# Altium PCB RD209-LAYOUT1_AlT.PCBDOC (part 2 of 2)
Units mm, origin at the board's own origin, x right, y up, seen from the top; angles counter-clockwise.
Board outline 152.4 x 152.4 mm, 4 copper layers (TOP, Mid-Layer 1, Mid-Layer 2, BOTTOM), stack 0.711 mm thick; 246 components, 168 nets, 761 pads, 266 vias.
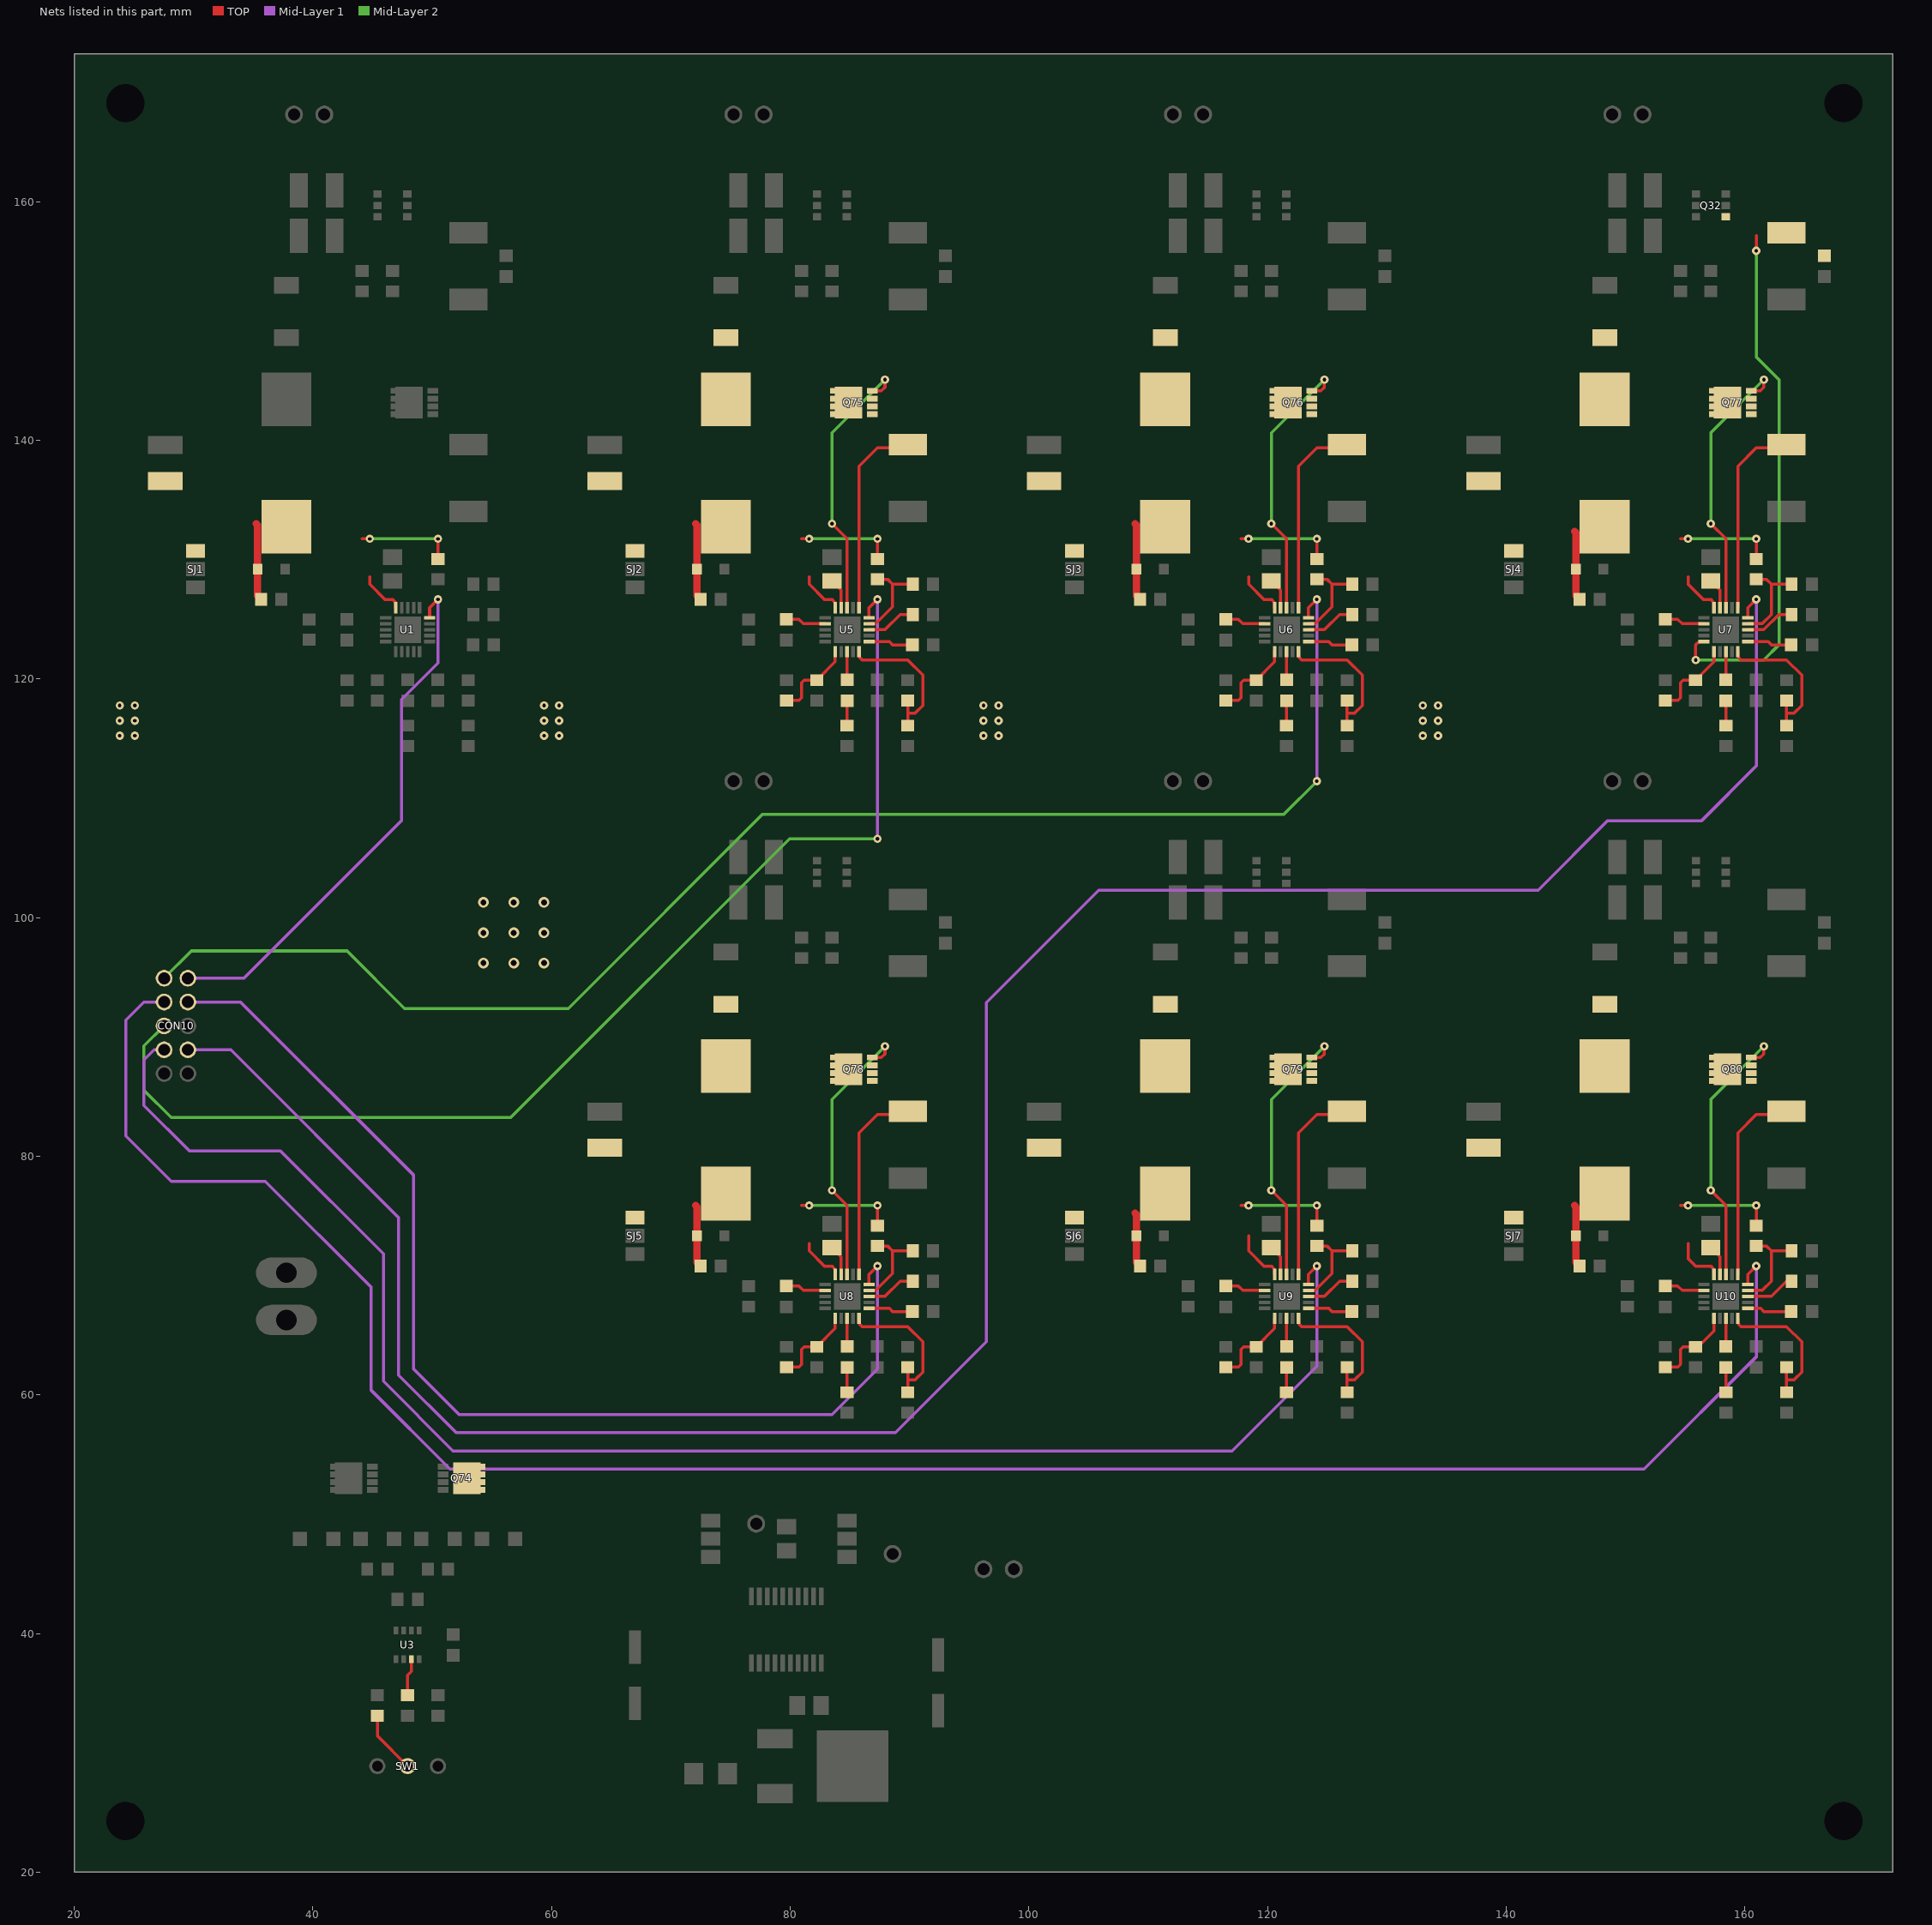
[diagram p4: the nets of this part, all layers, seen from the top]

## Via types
v1: diameter 0.7, hole 0.3, TOP to BOTTOM, tented both sides, 257 vias
v2: diameter 0.9, hole 0.5, TOP to BOTTOM, 9 vias

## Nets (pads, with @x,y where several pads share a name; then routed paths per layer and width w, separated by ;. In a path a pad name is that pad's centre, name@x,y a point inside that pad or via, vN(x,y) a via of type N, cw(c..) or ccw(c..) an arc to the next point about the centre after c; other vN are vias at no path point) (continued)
N_249: R131.1 R132.1 U5.5 | length 12.6
  TOP w0.254: U5.5@85.77,122.3 85.77,121.87 86.04,121.6 89.85,121.6 91.12,120.33 91.12,117.79 90.485,117.155 89.85,117.155 ; R132.1@89.85,116.1 89.85,117.155 ; R131.1@89.85,118.21 89.85,117.155
N_251: C27.2 U5.14 | length 2.6
  TOP w0.254: C27.2@83.5,128.22 84.27,127.45 U5.14@84.27,125.98
N_252: R133.1 U5.8 | length 4.2
  TOP w0.254: U5.8@86.61,124.14 87.945,124.14 89.215,125.41 R133.1@90.27,125.41
N_253: C28.2 U5.6 | length 3.7
  TOP w0.254: U5.6@86.61,123.14 88.31,123.14 88.58,122.87 C28.2@90.245,122.87
N_254: R134.2 R135.1 U5.9 | length 7.6
  TOP w0.254: U5.9@86.61,124.64 87.175,124.64 88.58,126.045 88.58,127.95 ; R135.1@87.31,128.37 88.16,128.37 88.58,127.95 ; R134.2@90.27,127.95 88.58,127.95
N_255: Q75.4 U5.13 | length 23.3
  TOP w0.254: v1(83.5,133.03) 84.77,131.76 U5.13@84.77,125.98 ; Q75.4@86.89,144.165 87.65,144.165 87.945,144.46 v1(87.945,145.095)
  Mid-Layer 2 w0.254: v1(83.5,133.03) 83.5,140.65 v1(87.945,145.095)
N_256: D48.A L2.2 Q75.5 Q75.6 Q75.7 Q75.8 Q75.EP
N_257: Q75.1 Q75.2 Q75.3 R137.2 U5.11 | length 16.7
  TOP w0.254: U5.11@85.77,125.98 85.77,137.84 87.31,139.38 89.59,139.38 R137.2@89.85,139.64
N_258: C30.2 U5.3 | length 2.4
  TOP w0.254: C30.2@84.77,119.935 U5.3@84.77,122.3
N_259: C30.1 R136.2 | length 2.1
  TOP w0.254: R136.2@84.77,116.1 C30.1@84.77,118.185
N_260: C31.2 U5.17 | length 3.4
  TOP w0.254: C31.2@79.69,125.015 80.72,125.015 81.095,124.64 U5.17@82.93,124.64
N_261: R138.2 R139.1 U5.1 | length 7
  TOP w0.254: R139.1@79.69,118.21 80.745,118.21 80.96,118.425 80.96,119.695 81.175,119.91 R138.2@82.23,119.91 83.77,121.45 U5.1@83.77,122.3
N_264: R140.1 R141.1 U6.5 | length 12.6
  TOP w0.254: U6.5@122.6,122.3 122.6,121.87 122.87,121.6 126.68,121.6 127.95,120.33 127.95,117.79 127.315,117.155 126.68,117.155 ; R141.1@126.68,116.1 126.68,117.155 ; R140.1@126.68,118.21 126.68,117.155
N_266: C34.2 U6.14 | length 2.6
  TOP w0.254: C34.2@120.33,128.22 121.1,127.45 U6.14@121.1,125.98
N_267: R142.1 U6.8 | length 4.2
  TOP w0.254: U6.8@123.44,124.14 124.775,124.14 126.045,125.41 R142.1@127.1,125.41
N_268: C35.2 U6.6 | length 3.7
  TOP w0.254: U6.6@123.44,123.14 125.14,123.14 125.41,122.87 C35.2@127.075,122.87
N_269: R143.2 R144.1 U6.9 | length 7.6
  TOP w0.254: U6.9@123.44,124.64 124.005,124.64 125.41,126.045 125.41,127.95 ; R144.1@124.14,128.37 124.99,128.37 125.41,127.95 ; R143.2@127.1,127.95 125.41,127.95
N_270: Q76.4 U6.13 | length 23.3
  TOP w0.254: v1(120.33,133.03) 121.6,131.76 U6.13@121.6,125.98 ; Q76.4@123.72,144.165 124.48,144.165 124.775,144.46 v1(124.775,145.095)
  Mid-Layer 2 w0.254: v1(120.33,133.03) 120.33,140.65 v1(124.775,145.095)
N_271: D49.A L3.2 Q76.5 Q76.6 Q76.7 Q76.8 Q76.EP
N_272: Q76.1 Q76.2 Q76.3 R146.2 U6.11 | length 16.7
  TOP w0.254: U6.11@122.6,125.98 122.6,137.84 124.14,139.38 126.42,139.38 R146.2@126.68,139.64
N_273: C37.2 U6.3 | length 2.4
  TOP w0.254: C37.2@121.6,119.935 U6.3@121.6,122.3
N_274: C37.1 R145.2 | length 2.1
  TOP w0.254: R145.2@121.6,116.1 C37.1@121.6,118.185
N_275: C38.2 U6.17 | length 3.4
  TOP w0.254: C38.2@116.52,125.015 117.55,125.015 117.925,124.64 U6.17@119.76,124.64
N_276: R147.2 R148.1 U6.1 | length 7
  TOP w0.254: R148.1@116.52,118.21 117.575,118.21 117.79,118.425 117.79,119.695 118.005,119.91 R147.2@119.06,119.91 120.6,121.45 U6.1@120.6,122.3
N_279: R149.1 R150.1 U7.5 | length 12.6
  TOP w0.254: U7.5@159.43,122.3 159.43,121.87 159.7,121.6 163.51,121.6 164.78,120.33 164.78,117.79 164.145,117.155 163.51,117.155 ; R150.1@163.51,116.1 163.51,117.155 ; R149.1@163.51,118.21 163.51,117.155
N_281: C41.2 U7.14 | length 2.6
  TOP w0.254: C41.2@157.16,128.22 157.93,127.45 U7.14@157.93,125.98
N_282: R151.1 U7.8 | length 4.2
  TOP w0.254: U7.8@160.27,124.14 161.605,124.14 162.875,125.41 R151.1@163.93,125.41
N_283: C42.2 U7.6 | length 3.7
  TOP w0.254: U7.6@160.27,123.14 161.97,123.14 162.24,122.87 C42.2@163.905,122.87
N_284: R152.2 R153.1 U7.9 | length 8
  TOP w0.254: U7.9@160.27,124.64 161.47,124.64 162.24,125.41 162.24,127.95 ; R153.1@160.97,128.37 161.82,128.37 162.24,127.95 ; R152.2@163.93,127.95 162.24,127.95
N_285: Q77.4 U7.13 | length 23.3
  TOP w0.254: v1(157.16,133.03) 158.43,131.76 U7.13@158.43,125.98 ; Q77.4@160.55,144.165 161.31,144.165 161.605,144.46 v1(161.605,145.095)
  Mid-Layer 2 w0.254: v1(157.16,133.03) 157.16,140.65 v1(161.605,145.095)
N_286: D50.A L4.2 Q77.5 Q77.6 Q77.7 Q77.8 Q77.EP
N_287: Q77.1 Q77.2 Q77.3 R155.2 U7.11 | length 16.7
  TOP w0.254: U7.11@159.43,125.98 159.43,137.84 160.97,139.38 163.25,139.38 R155.2@163.51,139.64
N_288: C44.2 U7.3 | length 2.4
  TOP w0.254: C44.2@158.43,119.935 U7.3@158.43,122.3
N_289: C44.1 R154.2 | length 2.1
  TOP w0.254: R154.2@158.43,116.1 C44.1@158.43,118.185
N_290: C45.2 U7.17 | length 3.4
  TOP w0.254: C45.2@153.35,125.015 154.38,125.015 154.755,124.64 U7.17@156.59,124.64
N_291: R156.2 R157.1 U7.1 | length 7
  TOP w0.254: R157.1@153.35,118.21 154.405,118.21 154.62,118.425 154.62,119.695 154.835,119.91 R156.2@155.89,119.91 157.43,121.45 U7.1@157.43,122.3
N_292: C11.2 Q32.4 R67.2 U7.20 | length 44.7
  TOP w0.254: v1(155.89,121.6) 155.89,122.87 156.16,123.14 U7.20@156.59,123.14 ; v1(160.97,155.89) 160.97,157.16
  Mid-Layer 2 w0.254: v1(155.89,121.6) 161.605,121.6 162.875,122.87 162.875,145.095 160.97,147 v1(160.97,155.89)
N_294: R158.1 R159.1 U8.5 | length 12.6
  TOP w0.254: U8.5@85.77,66.42 85.77,65.99 86.04,65.72 89.85,65.72 91.12,64.45 91.12,61.91 90.485,61.275 89.85,61.275 ; R159.1@89.85,60.22 89.85,61.275 ; R158.1@89.85,62.33 89.85,61.275
N_296: C48.2 U8.14 | length 2.6
  TOP w0.254: C48.2@83.5,72.34 84.27,71.57 U8.14@84.27,70.1
N_297: R160.1 U8.8 | length 4.2
  TOP w0.254: U8.8@86.61,68.26 87.945,68.26 89.215,69.53 R160.1@90.27,69.53
N_298: C49.2 U8.6 | length 3.7
  TOP w0.254: U8.6@86.61,67.26 88.31,67.26 88.58,66.99 C49.2@90.245,66.99
N_299: R161.2 R162.1 U8.9 | length 7.6
  TOP w0.254: U8.9@86.61,68.76 87.175,68.76 88.58,70.165 88.58,72.07 ; R162.1@87.31,72.49 88.16,72.49 88.58,72.07 ; R161.2@90.27,72.07 88.58,72.07
N_300: Q78.4 U8.13 | length 23.3
  TOP w0.254: v1(83.5,77.15) 84.77,75.88 U8.13@84.77,70.1 ; Q78.4@86.89,88.285 87.65,88.285 87.945,88.58 v1(87.945,89.215)
  Mid-Layer 2 w0.254: v1(83.5,77.15) 83.5,84.77 v1(87.945,89.215)
N_301: D51.A L5.2 Q78.5 Q78.6 Q78.7 Q78.8 Q78.EP
N_302: Q78.1 Q78.2 Q78.3 R164.2 U8.11 | length 16.7
  TOP w0.254: U8.11@85.77,70.1 85.77,81.96 87.31,83.5 89.59,83.5 R164.2@89.85,83.76
N_303: C51.2 U8.3 | length 2.4
  TOP w0.254: C51.2@84.77,64.055 U8.3@84.77,66.42
N_304: C51.1 R163.2 | length 2.1
  TOP w0.254: R163.2@84.77,60.22 C51.1@84.77,62.305
N_305: C52.2 U8.17 | length 3.4
  TOP w0.254: C52.2@79.69,69.135 80.72,69.135 81.095,68.76 U8.17@82.93,68.76
N_306: R165.2 R166.1 U8.1 | length 7
  TOP w0.254: R166.1@79.69,62.33 80.745,62.33 80.96,62.545 80.96,63.815 81.175,64.03 R165.2@82.23,64.03 83.77,65.57 U8.1@83.77,66.42
N_309: R167.1 R168.1 U9.5 | length 12.6
  TOP w0.254: U9.5@122.6,66.42 122.6,65.99 122.87,65.72 126.68,65.72 127.95,64.45 127.95,61.91 127.315,61.275 126.68,61.275 ; R168.1@126.68,60.22 126.68,61.275 ; R167.1@126.68,62.33 126.68,61.275
N_311: C55.2 U9.14 | length 2.6
  TOP w0.254: C55.2@120.33,72.34 121.1,71.57 U9.14@121.1,70.1
N_312: R169.1 U9.8 | length 4.2
  TOP w0.254: U9.8@123.44,68.26 124.775,68.26 126.045,69.53 R169.1@127.1,69.53
N_313: C56.2 U9.6 | length 3.7
  TOP w0.254: U9.6@123.44,67.26 125.14,67.26 125.41,66.99 C56.2@127.075,66.99
N_314: R170.2 R171.1 U9.9 | length 12
  TOP w0.254: R171.1@124.14,72.49 124.99,72.49 125.41,72.07 ; R170.2@127.1,72.07 125.41,72.07 ; 124.005,68.76 125.41,70.165 ; 124.005,68.76 U9.9@123.44,68.76 124.005,68.76 ; 124.005,68.76 125.41,70.165 ; 125.41,70.165 125.41,72.07 ; 125.41,70.165 125.41,72.07
N_315: Q79.4 U9.13 | length 23.3
  TOP w0.254: v1(120.33,77.15) 121.6,75.88 U9.13@121.6,70.1 ; Q79.4@123.72,88.285 124.48,88.285 124.775,88.58 v1(124.775,89.215)
  Mid-Layer 2 w0.254: v1(120.33,77.15) 120.33,84.77 v1(124.775,89.215)
N_316: D52.A L6.2 Q79.5 Q79.6 Q79.7 Q79.8 Q79.EP
N_317: Q79.1 Q79.2 Q79.3 R173.2 U9.11 | length 16.7
  TOP w0.254: U9.11@122.6,70.1 122.6,81.96 124.14,83.5 126.42,83.5 R173.2@126.68,83.76
N_318: C58.2 U9.3 | length 2.4
  TOP w0.254: C58.2@121.6,64.055 U9.3@121.6,66.42
N_319: C58.1 R172.2 | length 2.1
  TOP w0.254: R172.2@121.6,60.22 C58.1@121.6,62.305
N_320: C59.2 U9.17 | length 3.4
  TOP w0.254: C59.2@116.52,69.135 117.55,69.135 117.925,68.76 U9.17@119.76,68.76
N_321: R174.2 R175.1 U9.1 | length 7
  TOP w0.254: R175.1@116.52,62.33 117.575,62.33 117.79,62.545 117.79,63.815 118.005,64.03 R174.2@119.06,64.03 120.6,65.57 U9.1@120.6,66.42
N_324: R176.1 R177.1 U10.5 | length 12.6
  TOP w0.254: U10.5@159.43,66.42 159.43,65.99 159.7,65.72 163.51,65.72 164.78,64.45 164.78,61.91 164.145,61.275 163.51,61.275 ; R177.1@163.51,60.22 163.51,61.275 ; R176.1@163.51,62.33 163.51,61.275
N_326: C62.2 U10.14 | length 2.6
  TOP w0.254: C62.2@157.16,72.34 157.93,71.57 U10.14@157.93,70.1
N_327: R178.1 U10.8 | length 4.2
  TOP w0.254: U10.8@160.27,68.26 162.24,68.26 163.51,69.53 R178.1@163.93,69.53
N_328: C63.2 U10.6 | length 3.7
  TOP w0.254: U10.6@160.27,67.26 161.335,67.26 161.605,66.99 C63.2@163.905,66.99
N_329: R179.2 R180.1 U10.9 | length 8
  TOP w0.254: U10.9@160.27,68.76 161.47,68.76 162.24,69.53 162.24,72.07 ; R180.1@160.97,72.49 161.82,72.49 162.24,72.07 ; R179.2@163.93,72.07 162.24,72.07
N_330: Q80.4 U10.13 | length 23.3
  TOP w0.254: v1(157.16,77.15) 158.43,75.88 U10.13@158.43,70.1 ; Q80.4@160.55,88.285 161.31,88.285 161.605,88.58 v1(161.605,89.215)
  Mid-Layer 2 w0.254: v1(157.16,77.15) 157.16,84.77 v1(161.605,89.215)
N_331: D53.A L7.2 Q80.5 Q80.6 Q80.7 Q80.8 Q80.EP
N_332: Q80.1 Q80.2 Q80.3 R182.2 U10.11 | length 16.7
  TOP w0.254: U10.11@159.43,70.1 159.43,81.96 160.97,83.5 163.25,83.5 R182.2@163.51,83.76
N_333: C65.2 U10.3 | length 2.4
  TOP w0.254: C65.2@158.43,64.055 U10.3@158.43,66.42
N_334: C65.1 R181.2 | length 2.1
  TOP w0.254: R181.2@158.43,60.22 C65.1@158.43,62.305
N_335: C66.2 U10.17 | length 3.4
  TOP w0.254: C66.2@153.35,69.135 154.38,69.135 154.755,68.76 U10.17@156.59,68.76
N_336: R183.2 R184.1 U10.1 | length 7.1
  TOP w0.254: R184.1@153.35,62.33 154.405,62.33 154.62,62.545 154.62,63.815 154.835,64.03 R183.2@155.89,64.03 156.105,64.03 157.43,65.355 U10.1@157.43,66.42
PWMDIM1: CON10.1 U1.10 | length 45
  TOP w0.254: U1.10@49.78,125.14 49.78,125.98 v1(50.48,126.68)
  Mid-Layer 1 w0.254: CON10.1@29.525,94.93 34.224,94.93 47.432,108.138 47.432,118.298 50.48,121.346 v1(50.48,126.68)
PWMDIM2: CON10.6 U5.10 | length 100.1
  TOP w0.254: U5.10@86.61,125.14 86.61,125.98 v1(87.31,126.68)
  Mid-Layer 1 w0.254: v1(87.31,106.614) v1(87.31,126.68)
  Mid-Layer 2 w0.254: CON10.6@27.525,90.93 25.842,89.247 25.842,85.532 28.128,83.246 56.576,83.246 79.944,106.614 v1(87.31,106.614)
  other v1: 87.31,106.614 87.31,106.614
PWMDIM3: CON10.2 U6.10 | length 124.5
  TOP w0.254: U6.10@123.44,125.14 123.44,125.98 v1(124.14,126.68)
  Mid-Layer 1 w0.254: v1(124.14,111.44) v1(124.14,126.68)
  Mid-Layer 2 w0.254: CON10.2@27.525,94.93 29.811,97.216 42.86,97.216 47.686,92.39 61.402,92.39 77.658,108.646 121.346,108.646 v1(124.14,111.44)
  other v1: 124.14,111.44 124.14,111.44
PWMDIM4: CON10.7 U7.10 | length 208.1
  TOP w0.254: U7.10@160.27,125.14 160.27,125.98 v1(160.97,126.68)
  Mid-Layer 1 w0.254: CON10.7@29.525,88.93 33.112,88.93 47.178,74.864 47.178,61.656 52.004,56.83 88.834,56.83 96.454,64.45 96.454,92.898 105.852,102.296 142.682,102.296 148.524,108.138 156.398,108.138 160.97,112.71 v1(160.97,126.68)
PWMDIM5: CON10.3 U8.10 | length 93.7
  TOP w0.254: U8.10@86.61,69.26 86.61,70.1 v1(87.31,70.8)
  Mid-Layer 1 w0.254: CON10.3@29.525,92.93 33.938,92.93 48.448,78.42 48.448,62.164 52.258,58.354 83.5,58.354 87.31,62.164 v1(87.31,70.8)
PWMDIM6: CON10.8 U9.10 | length 135.5
  TOP w0.254: U9.10@123.44,69.26 123.44,70.1 v1(124.14,70.8)
  Mid-Layer 1 w0.254: CON10.8@27.525,88.93 26.7,88.93 25.842,88.072 25.842,84.262 29.652,80.452 37.272,80.452 45.908,71.816 45.908,61.148 51.75,55.306 117.028,55.306 124.14,62.418 v1(124.14,70.8)
PWMDIM7: CON10.4 U10.10 | length 180.1
  TOP w0.254: U10.10@160.27,69.26 160.27,70.1 v1(160.97,70.8)
  Mid-Layer 1 w0.254: CON10.4@27.525,92.93 25.842,92.93 24.318,91.406 24.318,81.722 28.128,77.912 36.002,77.912 44.892,69.022 44.892,60.386 51.496,53.782 151.572,53.782 160.97,63.18 v1(160.97,70.8)
VCC: C1.2 C29.2 C36.2 C43.2 C50.2 C57.2 C64.2 L1.1 L2.1 L3.1 L4.1 L5.1 L6.1 L7.1 Q74.5 Q74.6 Q74.7 Q74.8 Q74.EP R1.2 R119.2 R121.2 R123.2 R135.2 R144.2 R153.2 R162.2 R171.2 R180.2 R186.2 R188.2 R190.2 R192.2 SJ1.3 SJ2.3 SJ3.3 SJ4.3 SJ5.3 SJ6.3 SJ7.3 U1.15 U5.15 U6.15 U7.15 U8.15 U9.15 U10.15 ZD55.A ZD56.A ZD57.A ZD58.A ZD59.A ZD60.A ZD61.A | length 125
  TOP w0.254: 44.13,131.76 v1(44.765,131.76) ; 44.765,128.585 44.765,127.95 46.035,126.68 46.67,126.68 46.94,126.41 U1.15@46.94,125.98 ; R1.2@50.48,130.07 v1(50.48,131.76) ; 80.96,75.88 v1(81.595,75.88) ; 80.96,131.76 v1(81.595,131.76) ; 81.595,72.705 81.595,72.07 82.865,70.8 83.5,70.8 83.77,70.53 U8.15@83.77,70.1 ; 81.595,128.585 81.595,127.95 82.865,126.68 83.5,126.68 83.77,126.41 U5.15@83.77,125.98 ; R162.2@87.31,74.19 v1(87.31,75.88) ; R135.2@87.31,130.07 v1(87.31,131.76) ; 117.79,75.88 v1(118.425,75.88) ; 117.79,131.76 v1(118.425,131.76) ; 118.425,73.34 118.425,72.07 119.695,70.8 120.33,70.8 120.6,70.53 U9.15@120.6,70.1 ; 118.425,128.585 118.425,127.95 119.695,126.68 120.33,126.68 120.6,126.41 U6.15@120.6,125.98 ; R171.2@124.14,74.19 v1(124.14,75.88) ; R144.2@124.14,130.07 v1(124.14,131.76) ; 154.62,75.88 v1(155.255,75.88) ; 154.62,131.76 v1(155.255,131.76) ; 155.255,72.705 155.255,71.435 155.89,70.8 157.16,70.8 157.43,70.53 U10.15@157.43,70.1 ; 155.255,128.585 155.255,127.95 156.525,126.68 157.16,126.68 157.43,126.41 U7.15@157.43,125.98 ; R180.2@160.97,74.19 v1(160.97,75.88) ; R153.2@160.97,130.07 v1(160.97,131.76)
  TOP w0.61: 35.24,133.03 35.36,132.91 ZD55.A@35.36,129.22 35.36,126.98 R119.2@35.66,126.68 ; 72.07,75.88 72.19,75.76 ZD59.A@72.19,73.34 72.19,71.1 R188.2@72.49,70.8 ; 72.07,133.03 72.19,132.91 ZD56.A@72.19,129.22 72.19,126.98 R121.2@72.49,126.68 ; 108.9,75.245 109.02,75.125 ZD60.A@109.02,73.34 109.02,71.1 R190.2@109.32,70.8 ; 108.9,133.03 109.02,132.91 ZD57.A@109.02,129.22 109.02,126.98 R123.2@109.32,126.68 ; 145.73,75.88 145.85,75.76 ZD61.A@145.85,73.34 145.85,71.1 R192.2@146.15,70.8 ; 145.73,132.395 145.85,132.275 ZD58.A@145.85,129.22 145.85,126.98 R186.2@146.15,126.68
  Mid-Layer 2 w0.254: v1(44.765,131.76) v1(50.48,131.76) ; v1(81.595,75.88) v1(87.31,75.88) ; v1(81.595,131.76) v1(87.31,131.76) ; v1(118.425,75.88) v1(124.14,75.88) ; v1(118.425,131.76) v1(124.14,131.76) ; v1(155.255,75.88) v1(160.97,75.88) ; v1(155.255,131.76) v1(160.97,131.76)
  other v1: 23.81,115.25 25.08,115.25 59.37,115.25 60.64,115.25 96.2,115.25 97.47,115.25 133.03,115.25 134.3,115.25 23.81,116.52 25.08,116.52 59.37,116.52 60.64,116.52 96.2,116.52 97.47,116.52 133.03,116.52 134.3,116.52 23.81,117.79 25.08,117.79 59.37,117.79 60.64,117.79 96.2,117.79 97.47,117.79 133.03,117.79 134.3,117.79
  other v2: 54.29,96.2 56.83,96.2 59.37,96.2 54.29,98.74 56.83,98.74 59.37,98.74 54.29,101.28 56.83,101.28 59.37,101.28
VDD_7104_DIAG: R126.1 U3.7 | length 3.2
  TOP w0.254: R126.1@47.94,34.82 47.94,36.51 48.265,36.835 U3.7@48.265,37.85
VDD_7104_IN: R127.1 SW1.2 | length 5.3
  TOP w0.254: R127.1@45.4,33.12 45.4,31.43 SW1.2@47.94,28.89
pads on no net: CON10.9 IC4.4 IC4.6 IC4.9 IC4.12 IC4.18 SW1.1 U1.7 U3.4 U5.7 U6.7 U7.7 U8.7 U9.7 U10.7

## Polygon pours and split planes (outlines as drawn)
VCC on TOP "TOP99" (solid, pour order 111): 155.89,72.07 154.62,72.07 154.62,74.61 131.76,74.61 131.76,81.595 155.89,81.595
GND on TOP "TOP98" (solid, pour order 110): 20.475,20.4 cw(c20.475,20.475) 20.4,20.475 20.4,171.925 cw(c20.475,171.925) 20.475,172 171.925,172 cw(c171.925,171.925) 172,171.925 172,20.475 cw(c171.925,20.475) 171.925,20.4
VCC on TOP "TOP87" (solid, pour order 99): 155.89,127.95 154.62,127.95 154.62,130.49 131.76,130.49 131.76,137.475 155.89,137.475
LV1 on TOP "TOP19" (solid, pour order 31): 33.97,128.585 26.35,128.585 26.35,129.855 33.97,129.855
N_9 on TOP "TOP43" (solid, pour order 55): 55.56,143.825 55.56,138.11 49.845,138.11 49.845,143.661 50.51,143.661 ccw(c50.51,143.915) 50.728,143.784 50.978,143.784 51.019,143.825
LED-1 on TOP "TOP48" (solid, pour order 60): 48.575,159.383 44.765,159.383 44.765,163.51 48.575,163.51
N_220 on TOP "TOP58" (solid, pour order 70): 56.83,155.255 47.623,155.255 47.623,159.065 56.83,159.065
LED+1 on TOP "TOP77" (solid, pour order 89): 39.685,152.08 35.875,152.08 35.875,163.51 39.685,163.51
LV1 on TOP "TOP90" (solid, pour order 102): 56.83,145.73 51.115,145.73 51.115,153.985 56.83,153.985
N_8 on TOP "TOP91" (solid, pour order 103): 49.21,140.65 35.24,140.65 35.24,149.54 49.21,149.54
LV1 on TOP "TOP18" (solid, pour order 30): 44.13,120.965 41.59,120.965 41.59,122.235 44.13,122.235
N_221 on TOP "TOP56" (solid, pour order 68): 41.59,124.14 37.145,124.14 37.145,129.855 43.495,129.855 43.495,127.95 45.4,126.045 45.4,125.41 44.13,125.41 44.13,126.045 41.59,126.045
VCC on TOP "TOP81" (solid, pour order 93): 25.715,113.98 22.54,113.98 22.54,134.935 25.715,134.935
VCC on TOP "TOP85" (solid, pour order 97): 45.4,127.95 44.13,127.95 44.13,130.49 22.54,130.49 22.54,137.475 45.4,137.475
LV2 on TOP "TOP16" (solid, pour order 28): 70.8,128.585 63.18,128.585 63.18,129.855 70.8,129.855
VCC on TOP "TOP82" (solid, pour order 94): 61.91,113.98 58.1,113.98 58.1,134.935 61.91,134.935
LED-2 on TOP "TOP4" (solid, pour order 16): 85.405,159.383 81.595,159.383 81.595,163.51 85.405,163.51
LV2 on TOP "TOP17" (solid, pour order 29): 93.66,145.73 87.945,145.73 87.945,153.985 93.66,153.985
LED+2 on TOP "TOP39" (solid, pour order 51): 76.515,152.08 72.705,152.08 72.705,163.51 76.515,163.51
N_257 on TOP "TOP40" (solid, pour order 52): 92.39,143.825 92.39,138.11 86.675,138.11 86.675,143.661 87.34,143.661 ccw(c87.34,143.915) 87.558,143.784 87.808,143.784 87.849,143.825
N_208 on TOP "TOP52" (solid, pour order 64): 78.42,124.14 73.975,124.14 73.975,129.855 80.325,129.855 80.325,127.95 82.23,126.045 82.23,125.41 80.96,125.41 80.96,126.045 78.42,126.045
LV2 on TOP "TOP55" (solid, pour order 67): 80.96,120.965 78.42,120.965 78.42,122.235 80.96,122.235
N_214 on TOP "TOP59" (solid, pour order 71): 93.66,155.255 84.453,155.255 84.453,159.065 93.66,159.065
N_256 on TOP "TOP76" (solid, pour order 88): 86.04,140.65 72.07,140.65 72.07,149.54 86.04,149.54
VCC on TOP "TOP86" (solid, pour order 98): 82.23,127.95 80.96,127.95 80.96,130.49 58.1,130.49 58.1,137.475 82.23,137.475
LED-3 on TOP "TOP3" (solid, pour order 15): 122.235,159.383 118.425,159.383 118.425,163.51 122.235,163.51
LED+3 on TOP "TOP22" (solid, pour order 34): 113.345,152.08 109.535,152.08 109.535,163.51 113.345,163.51
LV3 on TOP "TOP54" (solid, pour order 66): 130.49,145.73 124.775,145.73 124.775,153.985 130.49,153.985
N_218 on TOP "TOP60" (solid, pour order 72): 130.49,155.255 121.283,155.255 121.283,159.065 130.49,159.065
N_272 on TOP "TOP74" (solid, pour order 86): 129.22,143.825 129.22,138.11 123.505,138.11 123.505,143.661 124.17,143.661 ccw(c124.17,143.915) 124.388,143.784 124.638,143.784 124.679,143.825
N_271 on TOP "TOP75" (solid, pour order 87): 122.87,140.65 108.9,140.65 108.9,149.54 122.87,149.54
LV4 on TOP "TOP13" (solid, pour order 25): 167.32,145.73 161.605,145.73 161.605,153.985 167.32,153.985
N_287 on TOP "TOP38" (solid, pour order 50): 166.05,143.825 166.05,138.11 160.335,138.11 160.335,143.661 161,143.661 ccw(c161,143.915) 161.218,143.784 161.468,143.784 161.509,143.825
LED-4 on TOP "TOP47" (solid, pour order 59): 159.065,159.383 155.255,159.383 155.255,163.51 159.065,163.51
LED+4 on TOP "TOP71" (solid, pour order 83): 150.175,152.08 146.365,152.08 146.365,163.51 150.175,163.51
N_292 on TOP "TOP72" (solid, pour order 84): 167.32,155.255 158.113,155.255 158.113,159.065 167.32,159.065
N_286 on TOP "TOP73" (solid, pour order 85): 159.7,140.65 145.73,140.65 145.73,149.54 159.7,149.54
LV4 on TOP "TOP11" (solid, pour order 23): 154.62,120.965 152.08,120.965 152.08,122.235 154.62,122.235
LV4 on TOP "TOP12" (solid, pour order 24): 144.46,128.585 136.84,128.585 136.84,129.855 144.46,129.855
VCC on TOP "TOP44" (solid, pour order 56): 135.57,113.98 131.76,113.98 131.76,134.935 135.57,134.935
N_222 on TOP "TOP51" (solid, pour order 63): 152.08,124.14 147.635,124.14 147.635,129.855 153.985,129.855 153.985,127.95 155.89,126.045 155.89,125.41 154.62,125.41 154.62,126.045 152.08,126.045
N_219 on TOP "TOP5" (solid, pour order 17): 115.25,124.14 110.805,124.14 110.805,129.855 117.155,129.855 117.155,127.95 119.06,126.045 119.06,125.41 117.79,125.41 117.79,126.045 115.25,126.045
LV3 on TOP "TOP14" (solid, pour order 26): 117.79,120.965 115.25,120.965 115.25,122.235 117.79,122.235
LV3 on TOP "TOP15" (solid, pour order 27): 107.63,128.585 100.01,128.585 100.01,129.855 107.63,129.855
VCC on TOP "TOP45" (solid, pour order 57): 119.06,127.95 117.79,127.95 117.79,130.49 94.93,130.49 94.93,137.475 119.06,137.475
VCC on TOP "TOP83" (solid, pour order 95): 98.74,113.98 94.93,113.98 94.93,134.935 98.74,134.935
LV7 on TOP "TOP27" (solid, pour order 39): 167.32,89.85 161.605,89.85 161.605,98.105 167.32,98.105
N_332 on TOP "TOP63" (solid, pour order 75): 166.05,87.945 166.05,82.23 160.335,82.23 160.335,87.781 161,87.781 ccw(c161,88.035) 161.218,87.904 161.468,87.904 161.509,87.945
LED-6 on TOP "TOP1" (solid, pour order 13): 122.235,103.503 118.425,103.503 118.425,107.63 122.235,107.63
LV7 on TOP "TOP6" (solid, pour order 18): 154.62,65.085 152.08,65.085 152.08,66.355 154.62,66.355
LV6 on TOP "TOP7" (solid, pour order 19): 117.79,65.085 115.25,65.085 115.25,66.355 117.79,66.355
LV6 on TOP "TOP8" (solid, pour order 20): 107.63,72.705 100.01,72.705 100.01,73.975 107.63,73.975
LV5 on TOP "TOP10" (solid, pour order 22): 70.8,72.705 63.18,72.705 63.18,73.975 70.8,73.975
N_209 on TOP "TOP20" (solid, pour order 32): 130.49,99.375 121.283,99.375 121.283,103.185 130.49,103.185
LED-7 on TOP "TOP23" (solid, pour order 35): 159.065,103.503 155.255,103.503 155.255,107.63 159.065,107.63
N_224 on TOP "TOP25" (solid, pour order 37): 115.25,68.26 110.805,68.26 110.805,73.975 117.155,73.975 117.155,72.07 119.06,70.165 119.06,69.53 117.79,69.53 117.79,70.165 115.25,70.165
LV7 on TOP "TOP26" (solid, pour order 38): 144.46,72.705 136.84,72.705 136.84,73.975 144.46,73.975
LV6 on TOP "TOP28" (solid, pour order 40): 130.49,89.85 124.775,89.85 124.775,98.105 130.49,98.105
LED+6 on TOP "TOP35" (solid, pour order 47): 113.345,96.2 109.535,96.2 109.535,107.63 113.345,107.63
N_317 on TOP "TOP36" (solid, pour order 48): 129.22,87.945 129.22,82.23 123.505,82.23 123.505,87.781 124.17,87.781 ccw(c124.17,88.035) 124.388,87.904 124.638,87.904 124.679,87.945
N_316 on TOP "TOP37" (solid, pour order 49): 122.87,84.77 108.9,84.77 108.9,93.66 122.87,93.66
N_159 on TOP "TOP42" (solid, pour order 54): 167.32,99.375 158.113,99.375 158.113,103.185 167.32,103.185
N_225 on TOP "TOP49" (solid, pour order 61): 152.08,68.26 147.635,68.26 147.635,73.975 153.985,73.975 153.985,72.07 155.89,70.165 155.89,69.53 154.62,69.53 154.62,70.165 152.08,70.165
LED+7 on TOP "TOP62" (solid, pour order 74): 150.175,96.2 146.365,96.2 146.365,107.63 150.175,107.63
N_331 on TOP "TOP64" (solid, pour order 76): 159.7,84.77 145.73,84.77 145.73,93.66 159.7,93.66
VCC on TOP "TOP80" (solid, pour order 92): 135.57,51.75 131.76,51.75 131.76,79.055 135.57,79.055
VCC on TOP "TOP93" (solid, pour order 105): 119.06,72.07 117.79,72.07 117.79,74.61 94.93,74.61 94.93,81.595 119.06,81.595
VCC on TOP "TOP94" (solid, pour order 106): 98.74,51.75 94.93,51.75 94.93,79.055 98.74,79.055
+12V on TOP "TOP96" (solid, pour order 108): 44.13,51.75 33.97,51.75 33.97,67.625 44.13,67.625
LED-5 on TOP "TOP2" (solid, pour order 14): 85.405,103.503 81.595,103.503 81.595,107.63 85.405,107.63
LV5 on TOP "TOP9" (solid, pour order 21): 80.96,65.085 78.42,65.085 78.42,66.355 80.96,66.355
LV5 on TOP "TOP29" (solid, pour order 41): 93.66,89.85 87.945,89.85 87.945,98.105 93.66,98.105
N_217 on TOP "TOP32" (solid, pour order 44): 93.66,99.375 84.453,99.375 84.453,103.185 93.66,103.185
VCC on TOP "TOP46" (solid, pour order 58): 82.23,72.07 80.96,72.07 80.96,74.61 58.735,74.61 58.735,81.595 82.23,81.595
N_223 on TOP "TOP50" (solid, pour order 62): 78.42,68.26 73.975,68.26 73.975,73.975 80.325,73.975 80.325,72.07 82.23,70.165 82.23,69.53 80.96,69.53 80.96,70.165 78.42,70.165
LED+5 on TOP "TOP68" (solid, pour order 80): 76.515,96.2 72.705,96.2 72.705,107.63 76.515,107.63
N_302 on TOP "TOP69" (solid, pour order 81): 92.39,87.945 92.39,82.23 86.675,82.23 86.675,87.781 87.34,87.781 ccw(c87.34,88.035) 87.558,87.904 87.808,87.904 87.849,87.945
N_301 on TOP "TOP70" (solid, pour order 82): 86.04,84.77 72.07,84.77 72.07,93.66 86.04,93.66
VCC on TOP "TOP79" (solid, pour order 91): 61.275,103.82 61.275,51.75 51.75,51.75 51.75,103.82
VCC on TOP "TOP95" (solid, pour order 107): 135.57,56.83 135.57,51.75 51.75,51.75 51.75,56.83
N_54 on TOP "TOP21" (solid, pour order 33): 80.325,29.525 80.325,25.715 73.975,25.715 73.975,29.525
N_235 on TOP "TOP41" (solid, pour order 53): 49.845,44.765 46.035,44.765 46.035,53.655 49.845,53.655
+12V on TOP "TOP78" (solid, pour order 90): 72.705,35.875 72.705,25.715 58.735,25.715 58.735,35.875
+5V on TOP "TOP89" (solid, pour order 101): 82.305,25.715 cw(c82.305,25.79) 82.23,25.79 82.23,35.165 cw(c82.305,35.165) 82.305,35.24 96.2,35.24 97.724,36.764 97.724,46.341 cw(c97.799,46.341) 97.799,46.416 99.681,46.416 cw(c99.681,46.341) 99.756,46.341 99.756,25.79 cw(c99.681,25.79) 99.681,25.715
N_235 on TOP "TOP97" (solid, pour order 109): 51.115,56.83 51.115,52.549 50.45,52.549 ccw(c50.45,52.295) 50.224,52.412 50.21,52.385 49.845,52.385 49.845,51.115 44.765,51.115 44.765,53.491 45.43,53.491 ccw(c45.43,53.745) 45.655,53.628 45.67,53.655 46.035,53.655 46.035,56.83
LV1 on Mid-Layer 1 "MID1100" (solid, pour order 5): 26.425,116.52 cw(c26.425,116.595) 26.35,116.595 26.35,149.465 cw(c26.425,149.465) 26.425,149.54 51.115,149.54 51.115,153.91 cw(c51.19,153.91) 51.19,153.985 56.755,153.985 cw(c56.755,153.91) 56.83,153.91 56.83,145.805 cw(c56.755,145.805) 56.755,145.73 33.97,145.73 33.97,122.235 39.555,122.235 cw(c39.555,122.16) 39.572,122.087 ccw(c39.685,121.6) 39.798,122.087 cw(c39.815,122.16) 39.815,122.235 44.055,122.235 cw(c44.055,122.16) 44.13,122.16 44.13,116.595 cw(c44.055,116.595) 44.055,116.52
LV2 on Mid-Layer 1 "MID1101" (solid, pour order 6): 63.255,116.52 cw(c63.255,116.595) 63.18,116.595 63.18,149.465 cw(c63.255,149.465) 63.255,149.54 87.945,149.54 87.945,153.91 cw(c88.02,153.91) 88.02,153.985 93.585,153.985 cw(c93.585,153.91) 93.66,153.91 93.66,145.805 cw(c93.585,145.805) 93.585,145.73 70.8,145.73 70.8,122.235 76.385,122.235 cw(c76.385,122.16) 76.402,122.087 ccw(c76.515,121.6) 76.628,122.087 cw(c76.645,122.16) 76.645,122.235 80.885,122.235 cw(c80.885,122.16) 80.96,122.16 80.96,116.595 cw(c80.885,116.595) 80.885,116.52
LV3 on Mid-Layer 1 "MID1102" (solid, pour order 7): 100.085,116.52 cw(c100.085,116.595) 100.01,116.595 100.01,149.465 cw(c100.085,149.465) 100.085,149.54 124.775,149.54 124.775,153.91 cw(c124.85,153.91) 124.85,153.985 130.415,153.985 cw(c130.415,153.91) 130.49,153.91 130.49,145.805 cw(c130.415,145.805) 130.415,145.73 107.63,145.73 107.63,122.235 113.215,122.235 cw(c113.215,122.16) 113.232,122.087 ccw(c113.345,121.6) 113.458,122.087 cw(c113.475,122.16) 113.475,122.235 117.715,122.235 cw(c117.715,122.16) 117.79,122.16 117.79,116.595 cw(c117.715,116.595) 117.715,116.52
LV4 on Mid-Layer 1 "MID1103" (solid, pour order 8): 136.915,116.52 cw(c136.915,116.595) 136.84,116.595 136.84,149.465 cw(c136.915,149.465) 136.915,149.54 161.605,149.54 161.605,153.91 cw(c161.68,153.91) 161.68,153.985 167.245,153.985 cw(c167.245,153.91) 167.32,153.91 167.32,145.805 cw(c167.245,145.805) 167.245,145.73 144.46,145.73 144.46,122.235 150.045,122.235 cw(c150.045,122.16) 150.062,122.087 ccw(c150.175,121.6) 150.288,122.087 cw(c150.305,122.16) 150.305,122.235 154.545,122.235 cw(c154.545,122.16) 154.62,122.16 154.62,116.595 cw(c154.545,116.595) 154.545,116.52
LV5 on Mid-Layer 1 "MID1104" (solid, pour order 9): 63.255,60.64 cw(c63.255,60.715) 63.18,60.715 63.18,93.585 cw(c63.255,93.585) 63.255,93.66 87.945,93.66 87.945,98.03 cw(c88.02,98.03) 88.02,98.105 93.585,98.105 cw(c93.585,98.03) 93.66,98.03 93.66,89.925 cw(c93.585,89.925) 93.585,89.85 70.8,89.85 70.8,66.355 76.385,66.355 cw(c76.385,66.28) 76.402,66.207 ccw(c76.515,65.72) 76.628,66.207 cw(c76.645,66.28) 76.645,66.355 80.885,66.355 cw(c80.885,66.28) 80.96,66.28 80.96,60.715 cw(c80.885,60.715) 80.885,60.64
LV6 on Mid-Layer 1 "MID1105" (solid, pour order 10): 100.085,60.64 cw(c100.085,60.715) 100.01,60.715 100.01,93.585 cw(c100.085,93.585) 100.085,93.66 124.775,93.66 124.775,98.03 cw(c124.85,98.03) 124.85,98.105 130.415,98.105 cw(c130.415,98.03) 130.49,98.03 130.49,89.925 cw(c130.415,89.925) 130.415,89.85 107.63,89.85 107.63,66.355 113.215,66.355 cw(c113.215,66.28) 113.232,66.207 ccw(c113.345,65.72) 113.458,66.207 cw(c113.475,66.28) 113.475,66.355 117.715,66.355 cw(c117.715,66.28) 117.79,66.28 117.79,60.715 cw(c117.715,60.715) 117.715,60.64
LV7 on Mid-Layer 1 "MID1106" (solid, pour order 11): 136.915,60.64 cw(c136.915,60.715) 136.84,60.715 136.84,93.585 cw(c136.915,93.585) 136.915,93.66 161.605,93.66 161.605,98.03 cw(c161.68,98.03) 161.68,98.105 167.245,98.105 cw(c167.245,98.03) 167.32,98.03 167.32,89.925 cw(c167.245,89.925) 167.245,89.85 144.46,89.85 144.46,66.355 150.045,66.355 cw(c150.045,66.28) 150.062,66.207 ccw(c150.175,65.72) 150.288,66.207 cw(c150.305,66.28) 150.305,66.355 154.545,66.355 cw(c154.545,66.28) 154.62,66.28 154.62,60.715 cw(c154.545,60.715) 154.545,60.64
+12V on Mid-Layer 1 "MID1107" (solid, pour order 12): 34.045,25.715 cw(c34.045,25.79) 33.97,25.79 33.97,67.55 cw(c34.045,67.55) 34.045,67.625 44.055,67.625 cw(c44.055,67.55) 44.13,67.55 44.13,35.875 72.63,35.875 cw(c72.63,35.8) 72.705,35.8 72.705,25.79 cw(c72.63,25.79) 72.63,25.715
VCC on Mid-Layer 2 "MID2108" (solid, pour order 3): 51.75,119.06 61.275,119.06 61.275,94.93 51.75,94.93
VCC on Mid-Layer 2 "MID2109" (solid, pour order 4): 22.615,113.98 cw(c22.615,114.055) 22.54,114.055 22.54,118.985 cw(c22.615,118.985) 22.615,119.06 135.495,119.06 cw(c135.495,118.985) 135.57,118.985 135.57,114.055 cw(c135.495,114.055) 135.495,113.98
GND on BOTTOM "BOTTOM110" (solid, pour order 2): 20.475,20.4 cw(c20.475,20.475) 20.4,20.475 20.4,171.925 cw(c20.475,171.925) 20.475,172 171.925,172 cw(c171.925,171.925) 172,171.925 172,20.475 cw(c171.925,20.475) 171.925,20.4

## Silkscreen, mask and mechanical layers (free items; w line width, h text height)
Top Overlay:
  text "CON2" at 35.24,167.32 h0.86 r90
  text "CON3" at 72.07,167.32 h0.86 r90
  text "CON4" at 108.9,167.32 h0.86 r90
  text "CON5" at 145.73,167.32 h0.86 r90
  text "Q12" at 85.756,162.148 h0.86 r270
  text "Q32" at 159.471,162.095 h0.86 r270
  text "Q22" at 122.618,162.089 h0.86 r270
  text "Q2" at 48.939,161.151 h0.86 r270
  text "C18" at 37.78,160.97 h0.71 r180
  text "C32" at 74.61,160.97 h0.71 r180
  text "C46" at 111.44,160.97 h0.71 r180
  text "C60" at 148.27,160.97 h0.71 r180
  text "R37" at 88.533,159.452 h0.86
  text "R22" at 51.742,159.406 h0.86
  text "R52" at 125.307,159.418 h0.86
  text "R67" at 162.263,159.419 h0.86
  text "C3" at 37.78,157.16 h0.71 r180
  text "C19" at 74.61,157.16 h0.71 r180
  text "C39" at 111.44,157.16 h0.71 r180
  text "C53" at 148.27,157.16 h0.71 r180
  text "C10" at 130.97,155.479 h0.71 r270
  text "C11" at 167.745,155.406 h0.71 r270
  text "C9" at 94.088,155.307 h0.71 r270
  text "R69" at 157.996,154.272 h0.86 r270
  text "R39" at 84.47,154.265 h0.86 r270
  text "R54" at 121.311,154.248 h0.86 r270
  text "R24" at 47.631,154.171 h0.86 r270
  text "C8" at 58.022,153.734 h0.71 r90
  text "R53" at 116.822,152.297 h0.86 r90
  text "R23" at 43.215,152.148 h0.86 r90
  text "R68" at 153.646,152.133 h0.86 r90
  text "R38" at 79.937,152.019 h0.86 r90
  text "D49" at 109.189,150.346 h0.86 r90
  text "D1" at 36.194,150.225 h0.86 r90
  text "D48" at 72.32,150.079 h0.86 r90
  text "D50" at 146.02,149.966 h0.86 r90
  text "Q1" at 46.035,143.19 h0.86 r90
  text "Q75" at 82.865,143.19 h0.86 r90
  text "Q76" at 119.695,143.19 h0.86 r90
  text "Q77" at 156.525,143.19 h0.86 r90
  text "C29" at 66.207,140.111 h0.71 r270
  text "C43" at 139.991,140.048 h0.71 r270
  text "L3" at 118.193,139.904 h0.86 r270
  text "L2" at 81.238,139.824 h0.86 r270
  text "L4" at 155.091,139.781 h0.86 r270
  text "L1" at 44.673,139.705 h0.86 r270
  text "C1" at 29.452,139.111 h0.71 r270
  text "C36" at 103.185,138.11 h0.71 r270
  text "R8" at 50.798,135.57 h0.86 r90
  text "R137" at 87.628,133.983 h0.86 r90
  text "R146" at 124.458,133.983 h0.86 r90
  text "R155" at 161.288,133.983 h0.86 r90
  text "C5" at 45.4,129.22 h0.71 r90
  text "R1" at 52.436,129.214 h0.86 r90
  text "C27" at 82.23,129.22 h0.71 r90
  text "C34" at 119.06,129.22 h0.71 r90
  text "C41" at 155.89,129.22 h0.71 r90
  text "R152" at 164.78,129.22 h0.86
  text "R135" at 89.26,129.008 h0.86 r90
  text "ZD55" at 39.05,128.903 h0.56
  text "R2" at 54.29,128.903 h0.86
  text "ZD56" at 75.563,128.903 h0.56
  text "R134" at 90.803,128.903 h0.86
  text "ZD57" at 112.393,128.903 h0.56
  text "R144" at 126.05,128.918 h0.86 r90
  text "R143" at 127.315,128.903 h0.86
  text "ZD58" at 149.223,128.903 h0.56
  text "R153" at 162.956,128.823 h0.86 r90
  text "R119" at 38.415,126.68 h0.86
  text "R121" at 75.245,126.68 h0.86
  text "R123" at 112.075,126.68 h0.86
  text "R186" at 148.905,126.68 h0.86
  text "SJ2" at 66.638,126.535 h0.86 r270
  text "SJ3" at 103.432,126.463 h0.86 r270
  text "SJ1" at 29.806,126.423 h0.86 r270
  text "U1" at 44.286,126.422 h0.56
  text "SJ4" at 140.583,126.418 h0.86 r270
  text "U7" at 154.633,126.399 h0.56
  text "U5" at 81.003,126.222 h0.56
  text "U6" at 117.928,126.208 h0.56
  text "R142" at 127.701,126.179 h0.86
  text "R133" at 90.908,126.128 h0.86
  text "R3" at 55.878,124.775 h0.86
  text "R151" at 166.685,124.775 h0.86
  text "C6" at 41.908,123.823 h0.71 r90
  text "C31" at 78.738,123.823 h0.71 r90
  text "C38" at 115.568,123.188 h0.71 r90
  text "C45" at 152.398,123.188 h0.71 r90
  text "R118" at 38.802,122.451 h0.86 r90
  text "C42" at 166.685,122.235 h0.71
  text "R122" at 112.51,121.658 h0.86 r90
  text "C2" at 54.29,120.965 h0.71
  text "C28" at 91.755,120.965 h0.71
  text "C35" at 128.585,120.965 h0.71
  text "R149" at 165.266,120.309 h0.86 r270
  text "R140" at 128.446,120.224 h0.86 r270
  text "R120" at 75.65,120.17 h0.86 r90
  text "R124" at 149.192,120.118 h0.86 r90
  text "R131" at 91.619,120.06 h0.86 r270
  text "C7" at 47.078,118.271 h0.71 r90
  text "R6" at 55.761,118.158 h0.86 r90
  text "C30" at 83.906,118.028 h0.71 r90
  text "C37" at 120.786,117.901 h0.71 r90
  text "R4" at 41.865,117.707 h0.86 r90
  text "C44" at 157.534,117.694 h0.71 r90
  text "C40" at 160.646,117.35 h0.71 r270
  text "C33" at 123.727,117.302 h0.71 r270
  text "C26" at 86.955,117.265 h0.71 r270
  text "C4" at 50.163,117.155 h0.71 r270
  text "R150" at 164.445,116.434 h0.86 r270
  text "R141" at 127.593,116.249 h0.86 r270
  text "R132" at 90.712,116.213 h0.86 r270
  text "R5" at 53.986,115.98 h0.86 r270
  text "R157" at 152.437,115.975 h0.86 r90
  text "R148" at 115.614,115.85 h0.86 r90
  text "R139" at 78.678,115.832 h0.86 r90
  text "R9" at 44.834,115.737 h0.86 r90
  text "R138" at 81.598,114.416 h0.86 r90
  text "R7" at 47.029,114.414 h0.86 r90
  text "R156" at 155.246,114.228 h0.86 r90
  text "R147" at 118.491,114.176 h0.86 r90
  text "R136" at 84.033,113.853 h0.86 r90
  text "R145" at 120.732,113.399 h0.86 r90
  text "R154" at 157.554,113.207 h0.86 r90
  text "CON6" at 72.07,111.44 h0.86 r90
  text "CON7" at 108.9,111.44 h0.86 r90
  text "CON8" at 145.73,111.44 h0.86 r90
  text "Q52" at 122.652,106.282 h0.86 r270
  text "Q62" at 159.463,106.24 h0.86 r270
  text "Q42" at 85.806,106.227 h0.86 r270
  text "C76" at 74.61,105.09 h0.71 r180
  text "C72" at 111.44,105.09 h0.71 r180
  text "C74" at 148.27,105.09 h0.71 r180
  text "R82" at 88.399,103.529 h0.86
  text "R112" at 162.077,103.511 h0.86
  text "R97" at 125.447,103.452 h0.86
  text "C75" at 74.61,101.28 h0.71 r180
  text "C67" at 111.44,101.28 h0.71 r180
  text "C73" at 148.27,101.28 h0.71 r180
  text "C13" at 130.898,99.807 h0.71 r270
  text "C14" at 167.69,99.692 h0.71 r270
  text "C12" at 94.2,99.449 h0.71 r270
  text "R114" at 158.203,98.413 h0.86 r270
  text "R99" at 121.298,98.331 h0.86 r270
  text "R84" at 84.489,98.237 h0.86 r270
  text "R83" at 80.026,96.365 h0.86 r90
  text "R98" at 116.52,96.2 h0.86 r90
  text "R113" at 153.602,95.702 h0.86 r90
  text "D52" at 109.535,94.93 h0.86 r90
  text "D52" at 109.535,94.93 h0.86 r90
  text "D53" at 145.909,94.537 h0.86 r90
  text "D51" at 72.443,94.048 h0.86 r90
  text "Q78" at 82.865,87.31 h0.86 r90
  text "Q79" at 119.695,87.31 h0.86 r90
  text "Q80" at 156.525,87.31 h0.86 r90
  text "CON10" at 33.97,86.04 h0.86 r90
  text "C64" at 139.918,84.205 h0.71 r270
  text "C50" at 66.214,84.072 h0.71 r270
  text "L6" at 118.19,83.942 h0.86 r270
  text "L5" at 81.374,83.877 h0.86 r270
  text "L7" at 155.037,83.816 h0.86 r270
  text "C57" at 103.185,82.23 h0.71 r270
  text "R164" at 87.628,78.42 h0.86 r90
  text "R173" at 124.458,78.103 h0.86 r90
  text "R182" at 161.288,78.103 h0.86 r90
  text "C48" at 82.23,73.34 h0.71 r90
  text "C55" at 119.06,73.34 h0.71 r90
  text "C62" at 155.89,73.34 h0.71 r90
  text "R162" at 89.223,73.049 h0.86 r90
  text "R171" at 126.036,73.042 h0.86 r90
  text "R180" at 162.918,73.042 h0.86 r90
  text "ZD59" at 75.563,73.023 h0.56
  text "R161" at 90.803,73.023 h0.86
  text "R170" at 127.633,73.023 h0.86
  text "ZD61" at 149.223,73.023 h0.56
  text "ZD60" at 111.967,73.004 h0.56
  text "R179" at 166.685,71.753 h0.86
  text "R188" at 75.245,70.8 h0.86
  text "R190" at 112.075,70.8 h0.86
  text "R192" at 148.905,70.8 h0.86
  text "U9" at 117.751,70.522 h0.56
  text "U8" at 80.928,70.468 h0.56
  text "R160" at 90.739,70.307 h0.86
  text "R169" at 127.595,70.284 h0.86
  text "SJ6" at 103.82,70.165 h0.86 r270
  text "SJ7" at 140.65,70.165 h0.86 r270
  text "SJ5" at 66.99,70.038 h0.86 r270
  text "U10" at 154.155,69.988 h0.56
  text "R178" at 166.685,69.213 h0.86
  text "C52" at 78.738,67.308 h0.71 r90
  text "C59" at 115.568,66.99 h0.71 r90
  text "C66" at 152.398,66.99 h0.71 r90
  text "C63" at 166.685,66.355 h0.71
  text "CON9" at 42.86,65.72 h0.86 r90
  text "C49" at 91.755,65.085 h0.71
  text "C56" at 128.585,65.085 h0.71
  text "R191" at 149.23,64.681 h0.86 r90
  text "R187" at 75.675,64.401 h0.86 r90
  text "R158" at 91.619,64.324 h0.86 r270
  text "R167" at 128.441,64.318 h0.86 r270
  text "R189" at 112.463,64.28 h0.86 r90
  text "R176" at 165.323,64.261 h0.86 r270
  text "C51" at 83.908,62.143 h0.71 r90
  text "C58" at 120.786,62.027 h0.71 r90
  text "C65" at 157.554,61.932 h0.71 r90
  text "C47" at 87.31,61.275 h0.71 r270
  text "C54" at 124.14,61.275 h0.71 r270
  text "C61" at 160.653,61.275 h0.71 r270
  text "R168" at 127.601,60.748 h0.86 r270
  text "R177" at 164.407,60.424 h0.86 r270
  text "R159" at 90.728,60.392 h0.86 r270
  text "R175" at 115.556,59.908 h0.86 r90
  text "R184" at 152.418,59.908 h0.86 r90
  text "R166" at 78.747,59.87 h0.86 r90
  text "R174" at 118.362,58.291 h0.86 r90
  text "R165" at 81.602,58.094 h0.86 r90
  text "R183" at 155.163,58.072 h0.86 r90
  text "R172" at 120.748,57.675 h0.86 r90
  text "R163" at 83.862,57.397 h0.86 r90
  text "R181" at 157.573,57.178 h0.86 r90
  text "Q74" at 54.787,54.508 h0.86 r270
  text "Q73" at 40.955,53.02 h0.86 r90
  text "P24" at 77.15,50.48 h0.86
  text "C69" at 80.96,49.845 h0.71 r270
  text "ZD44" at 39.692,48.975 h0.86
  text "ZD45" at 44.535,48.975 h0.86
  text "ZD46" at 49.277,48.918 h0.86
  text "SJ8" at 83.388,48.342 h0.86 r90
  text "SJ9" at 72.07,47.94 h0.86 r90
  text "P23" at 88.58,47.94 h0.86
  text "CON1" at 96.2,47.94 h0.86
  text "ZD47" at 58.013,47.466 h0.86
  text "R130" at 51.979,45.756 h0.86
  text "R129" at 40.067,43.954 h0.86
  text "R128" at 42.499,42.197 h0.86
  text "C70" at 70.8,39.685 h0.71 r270
  text "C71" at 96.2,39.05 h0.71 r270
  text "C21" at 52.763,39.008 h0.71 r270
  text "U3" at 44.203,38.541 h0.86
  text "IC4" at 73.412,37.032 h0.86
  text "R125" at 51.418,35.051 h0.86 r270
  text "C68" at 83.5,33.97 h0.71
  text "R127" at 44.434,32.622 h0.86 r90
  text "R126" at 46.342,31.414 h0.86
  text "R185" at 71.387,29.543 h0.86
  text "SW1" at 53.655,28.89 h0.86
  text "Q81" at 88.58,28.89 h0.86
